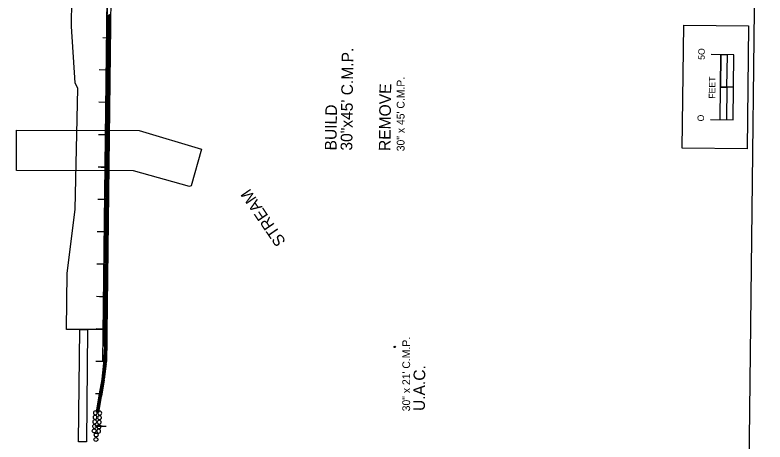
# Model space of a CAD drawing. Extents: x 16507806 to 16508824, y 7132703 to 7134669.
# Drawn here: x 16508245 to 16508824, y 7133461 to 7133791 of the extents above; entities that cross this region are included whole.
import ezdxf

# ---------------------------------------------------------------- set-up
doc = ezdxf.new("R2010")
doc.units = 0
for name, color, linetype in [('Default', 7, 'Continuous'), ('dsnCellElements', 7, 'Continuous'), ('dsnCellsScaleBlock', 7, 'Continuous'), ('EdgeShoulder', 7, 'Continuous'), ('NamedBoundary', 7, 'Continuous'), ('phoCulvert', 7, 'Continuous'), ('Shape', 7, 'Continuous'), ('SurSurveyPoints', 7, 'Continuous'), ('SurTxtDrainage', 7, 'Continuous'), ('Text', 7, 'Continuous'), ('TextAlignmentLrg', 7, 'Continuous'), ('TextAlignmentSml', 7, 'Continuous')]:
    doc.layers.add(name, color=color, linetype=linetype)

msp = doc.modelspace()

# ---------------------------------------------------------------- linework, layer by layer
at = {"layer": 'Default'}
msp.add_line((16508312.56, 7133523.48), (16508317.36, 7133923.45), dxfattribs=at)
for centre in [(16508317.59, 7133778.27), (16508317.64, 7133778.27), (16508317.44, 7133765.47), (16508317.44, 7133765.47), (16508317.29, 7133752.67), (16508317.29, 7133752.67), (16508317.11, 7133739.9), (16508317.15, 7133739.86), (16508316.96, 7133727.1), (16508316.96, 7133727.1), (16508316.82, 7133714.3), (16508316.82, 7133714.3), (16508316.67, 7133701.5), (16508316.67, 7133701.5), (16508316.52, 7133688.7), (16508316.52, 7133688.7), (16508316.38, 7133675.9), (16508316.38, 7133675.9), (16508316.23, 7133663.09), (16508316.23, 7133663.09), (16508316.08, 7133650.29), (16508316.08, 7133650.29), (16508315.94, 7133637.49), (16508315.94, 7133637.49), (16508315.79, 7133624.69), (16508315.79, 7133624.69), (16508315.64, 7133611.89), (16508315.64, 7133611.89), (16508315.5, 7133599.09), (16508315.5, 7133599.09), (16508315.35, 7133586.29), (16508315.35, 7133586.29), (16508315.15, 7133573.49), (16508315.2, 7133573.49), (16508315, 7133560.68), (16508315.06, 7133560.68), (16508314.91, 7133547.88)]:
    msp.add_circle(centre, 0.0521, dxfattribs=at)
for centre, start, end in [((16508317.78, 7133790.92), 359.34293, 179.34293), ((16508317.59, 7133778.12), 359.34293, 179.34293), ((16508317.64, 7133778.42), 179.34293, 359.34293), ((16508317.44, 7133765.62), 179.34293, 359.34293), ((16508317.44, 7133765.32), 359.34293, 179.34293), ((16508317.3, 7133752.82), 179.34293, 359.34293), ((16508317.29, 7133752.52), 359.34293, 179.34293), ((16508317.11, 7133739.75), 359.34293, 179.34293), ((16508317.15, 7133740.02), 179.34293, 359.34293), ((16508316.97, 7133727.25), 179.34293, 359.34293), ((16508316.96, 7133726.95), 359.34293, 179.34293), ((16508316.82, 7133714.15), 359.34293, 179.34293), ((16508316.82, 7133714.45), 179.34293, 359.34293), ((16508316.67, 7133701.65), 179.34293, 359.34293), ((16508316.67, 7133701.35), 359.34293, 179.34293), ((16508316.53, 7133688.85), 179.34293, 359.34293), ((16508316.52, 7133688.55), 359.34293, 179.34293), ((16508316.37, 7133675.74), 359.34293, 179.34293), ((16508316.38, 7133676.05), 179.34293, 359.34293), ((16508316.23, 7133663.25), 179.34293, 359.34293), ((16508316.23, 7133662.94), 359.34293, 179.34293), ((16508316.08, 7133650.44), 179.34293, 359.34293), ((16508316.08, 7133650.14), 359.34293, 179.34293), ((16508315.93, 7133637.34), 359.34293, 179.34293), ((16508315.94, 7133637.64), 179.34293, 359.34293), ((16508315.79, 7133624.84), 179.34293, 359.34293), ((16508315.79, 7133624.54), 359.34293, 179.34293), ((16508315.64, 7133612.04), 179.34293, 359.34293), ((16508315.64, 7133611.74), 359.34293, 179.34293), ((16508315.49, 7133598.94), 359.34293, 179.34293), ((16508315.5, 7133599.24), 179.34293, 359.34293), ((16508315.35, 7133586.44), 179.34293, 359.34293), ((16508315.35, 7133586.14), 359.34293, 179.34293), ((16508315.15, 7133573.33), 359.34293, 179.34293), ((16508315.2, 7133573.64), 179.34293, 359.34293), ((16508315, 7133560.84), 179.34293, 359.34293), ((16508315.05, 7133560.53), 359.34293, 179.34293), ((16508314.91, 7133548.03), 179.34293, 359.34293)]:
    msp.add_arc(centre, 0.281, start, end, dxfattribs=at)
at = {"layer": 'dsnCellElements'}
for p, q in [((16508316.7, 7133778.43), (16508316.85, 7133790.93)), ((16508318.72, 7133790.91), (16508316.85, 7133790.93)), ((16508317.3, 7133778.42), (16508317.45, 7133790.92)), ((16508317.98, 7133778.42), (16508318.12, 7133790.91)), ((16508318.58, 7133778.41), (16508318.72, 7133790.91)), ((16508316.5, 7133765.63), (16508316.65, 7133778.13)), ((16508318.52, 7133778.11), (16508316.65, 7133778.13)), ((16508318.58, 7133778.41), (16508316.7, 7133778.43)), ((16508317.1, 7133765.62), (16508317.25, 7133778.12)), ((16508317.78, 7133765.61), (16508317.92, 7133778.11)), ((16508318.38, 7133765.61), (16508318.52, 7133778.11)), ((16508316.36, 7133752.83), (16508316.5, 7133765.33)), ((16508318.38, 7133765.61), (16508316.5, 7133765.63)), ((16508318.38, 7133765.31), (16508316.5, 7133765.33)), ((16508316.96, 7133752.82), (16508317.1, 7133765.32)), ((16508317.63, 7133752.81), (16508317.78, 7133765.31)), ((16508318.23, 7133752.81), (16508318.38, 7133765.31)), ((16508316.21, 7133740.03), (16508316.35, 7133752.53)), ((16508318.23, 7133752.5), (16508316.35, 7133752.53)), ((16508318.23, 7133752.81), (16508316.36, 7133752.83)), ((16508316.81, 7133740.02), (16508316.95, 7133752.52)), ((16508317.49, 7133740.01), (16508317.63, 7133752.51)), ((16508318.09, 7133740.01), (16508318.23, 7133752.5)), ((16508316.03, 7133727.26), (16508316.17, 7133739.76)), ((16508318.05, 7133739.74), (16508316.17, 7133739.76)), ((16508318.09, 7133740.01), (16508316.21, 7133740.03)), ((16508316.63, 7133727.26), (16508316.77, 7133739.76)), ((16508317.3, 7133727.25), (16508317.45, 7133739.75)), ((16508317.9, 7133727.24), (16508318.05, 7133739.74)), ((16508315.88, 7133714.46), (16508316.02, 7133726.96)), ((16508317.9, 7133726.94), (16508316.02, 7133726.96)), ((16508317.9, 7133727.24), (16508316.03, 7133727.26)), ((16508316.48, 7133714.45), (16508316.62, 7133726.95)), ((16508317.16, 7133714.45), (16508317.3, 7133726.95)), ((16508317.76, 7133714.44), (16508317.9, 7133726.94)), ((16508315.73, 7133701.66), (16508315.88, 7133714.16)), ((16508317.76, 7133714.44), (16508315.88, 7133714.46)), ((16508317.75, 7133714.14), (16508315.88, 7133714.16)), ((16508316.33, 7133701.65), (16508316.48, 7133714.15)), ((16508317.01, 7133701.65), (16508317.15, 7133714.14)), ((16508317.61, 7133701.64), (16508317.75, 7133714.14)), ((16508315.59, 7133688.86), (16508315.73, 7133701.36)), ((16508317.61, 7133701.64), (16508315.73, 7133701.66)), ((16508317.61, 7133701.34), (16508315.73, 7133701.36)), ((16508316.19, 7133688.85), (16508316.33, 7133701.35)), ((16508316.86, 7133688.84), (16508317.01, 7133701.34)), ((16508317.46, 7133688.84), (16508317.61, 7133701.34)), ((16508315.44, 7133676.06), (16508315.58, 7133688.56)), ((16508317.46, 7133688.54), (16508315.58, 7133688.56)), ((16508317.46, 7133688.84), (16508315.59, 7133688.86)), ((16508316.04, 7133676.05), (16508316.18, 7133688.55)), ((16508316.72, 7133676.04), (16508316.86, 7133688.54)), ((16508317.32, 7133676.04), (16508317.46, 7133688.54)), ((16508315.29, 7133663.26), (16508315.44, 7133675.76)), ((16508317.32, 7133676.04), (16508315.44, 7133676.06)), ((16508317.31, 7133675.73), (16508315.44, 7133675.76)), ((16508315.89, 7133663.25), (16508316.04, 7133675.75)), ((16508316.57, 7133663.24), (16508316.71, 7133675.74)), ((16508317.17, 7133663.23), (16508317.31, 7133675.73)), ((16508315.15, 7133650.45), (16508315.29, 7133662.95)), ((16508317.17, 7133663.23), (16508315.29, 7133663.26)), ((16508317.17, 7133662.93), (16508315.29, 7133662.95)), ((16508315.75, 7133650.45), (16508315.89, 7133662.95)), ((16508316.42, 7133650.44), (16508316.57, 7133662.94)), ((16508317.02, 7133650.43), (16508317.17, 7133662.93)), ((16508315, 7133637.65), (16508315.14, 7133650.15)), ((16508317.02, 7133650.13), (16508315.14, 7133650.15)), ((16508317.02, 7133650.43), (16508315.15, 7133650.45)), ((16508315.6, 7133637.65), (16508315.74, 7133650.15)), ((16508316.28, 7133637.64), (16508316.42, 7133650.14)), ((16508316.88, 7133637.63), (16508317.02, 7133650.13)), ((16508316.88, 7133637.63), (16508315, 7133637.65)), ((16508314.85, 7133624.85), (16508315, 7133637.35)), ((16508316.87, 7133637.33), (16508315, 7133637.35)), ((16508315.45, 7133624.85), (16508315.6, 7133637.34)), ((16508316.13, 7133624.84), (16508316.27, 7133637.34)), ((16508316.73, 7133624.83), (16508316.87, 7133637.33)), ((16508314.71, 7133612.05), (16508314.85, 7133624.55)), ((16508316.73, 7133624.83), (16508314.85, 7133624.85)), ((16508316.72, 7133624.53), (16508314.85, 7133624.55)), ((16508315.31, 7133612.04), (16508315.45, 7133624.54)), ((16508315.98, 7133612.04), (16508316.12, 7133624.54)), ((16508316.58, 7133612.03), (16508316.72, 7133624.53)), ((16508314.56, 7133599.25), (16508314.7, 7133611.75)), ((16508316.58, 7133611.73), (16508314.7, 7133611.75)), ((16508316.58, 7133612.03), (16508314.71, 7133612.05)), ((16508315.16, 7133599.24), (16508315.3, 7133611.74)), ((16508315.83, 7133599.24), (16508315.98, 7133611.73)), ((16508316.43, 7133599.23), (16508316.58, 7133611.73)), ((16508314.41, 7133586.45), (16508314.56, 7133598.95)), ((16508316.43, 7133599.23), (16508314.56, 7133599.25)), ((16508316.43, 7133598.93), (16508314.56, 7133598.95)), ((16508315.01, 7133586.44), (16508315.16, 7133598.94)), ((16508315.69, 7133586.43), (16508315.83, 7133598.93)), ((16508316.29, 7133586.43), (16508316.43, 7133598.93)), ((16508314.27, 7133573.65), (16508314.41, 7133586.15)), ((16508316.29, 7133586.43), (16508314.41, 7133586.45)), ((16508316.28, 7133586.12), (16508314.41, 7133586.15)), ((16508314.87, 7133573.64), (16508315.01, 7133586.14)), ((16508315.54, 7133573.63), (16508315.68, 7133586.13)), ((16508316.14, 7133573.63), (16508316.28, 7133586.12)), ((16508314.07, 7133560.85), (16508314.21, 7133573.35)), ((16508316.09, 7133573.32), (16508314.21, 7133573.35)), ((16508316.14, 7133573.63), (16508314.27, 7133573.65)), ((16508314.67, 7133560.84), (16508314.81, 7133573.34)), ((16508315.34, 7133560.83), (16508315.49, 7133573.33)), ((16508315.94, 7133560.82), (16508316.09, 7133573.32)), ((16508313.97, 7133548.04), (16508314.12, 7133560.54)), ((16508315.94, 7133560.82), (16508314.07, 7133560.85)), ((16508315.99, 7133560.52), (16508314.12, 7133560.54)), ((16508314.57, 7133548.04), (16508314.72, 7133560.54)), ((16508315.25, 7133548.03), (16508315.39, 7133560.53)), ((16508315.85, 7133548.02), (16508315.99, 7133560.52)), ((16508313.77, 7133535.29), (16508313.91, 7133547.79)), ((16508313.91, 7133547.79), (16508315.79, 7133547.76)), ((16508315.85, 7133548.02), (16508313.97, 7133548.04)), ((16508314.37, 7133535.28), (16508314.51, 7133547.78)), ((16508315.04, 7133535.27), (16508315.19, 7133547.77)), ((16508315.64, 7133535.26), (16508315.79, 7133547.76)), ((16508313.77, 7133534.97), (16508313.21, 7133522.49)), ((16508313.77, 7133535.29), (16508315.64, 7133535.26)), ((16508315.64, 7133534.89), (16508313.77, 7133534.97)), ((16508314.37, 7133534.95), (16508313.81, 7133522.46)), ((16508315.04, 7133534.92), (16508314.49, 7133522.43)), ((16508315.64, 7133534.89), (16508315.09, 7133522.4)), ((16508313.2, 7133522.17), (16508311.84, 7133509.75)), ((16508313.8, 7133522.11), (16508312.44, 7133509.68)), ((16508314.47, 7133522.03), (16508313.11, 7133509.61)), ((16508315.06, 7133521.97), (16508313.2, 7133522.17)), ((16508315.09, 7133522.4), (16508313.21, 7133522.49)), ((16508315.06, 7133521.97), (16508313.7, 7133509.54)), ((16508311.81, 7133509.44), (16508309.62, 7133497.13)), ((16508312.4, 7133509.33), (16508310.21, 7133497.02)), ((16508313.06, 7133509.21), (16508310.88, 7133496.91)), ((16508313.65, 7133509.11), (16508311.47, 7133496.8)), ((16508313.65, 7133509.11), (16508311.81, 7133509.44)), ((16508313.7, 7133509.54), (16508311.84, 7133509.75)), ((16508309.57, 7133496.82), (16508307.39, 7133484.51)), ((16508310.16, 7133496.72), (16508307.98, 7133484.41)), ((16508310.83, 7133496.6), (16508308.64, 7133484.29)), ((16508311.42, 7133496.49), (16508309.23, 7133484.19)), ((16508311.42, 7133496.49), (16508309.57, 7133496.82)), ((16508311.47, 7133496.8), (16508309.62, 7133497.13)), ((16508309.23, 7133484.19), (16508307.39, 7133484.51))]:
    msp.add_line(p, q, dxfattribs=at)
msp.add_lwpolyline([(16508760.03, 7133688.07), (16508761.11, 7133783.07), (16508811.11, 7133782.5), (16508810.02, 7133687.5)], close=True, dxfattribs=at)
msp.add_lwpolyline([(16508760.03, 7133688.07), (16508761.11, 7133783.07), (16508811.11, 7133782.5), (16508810.02, 7133687.5)], close=True, dxfattribs=at)
at = {"layer": 'dsnCellsScaleBlock'}
msp.add_line((16508799.57, 7133735.13), (16508789.57, 7133735.24), dxfattribs=at)
msp.add_line((16508799.57, 7133735.13), (16508789.57, 7133735.24), dxfattribs=at)
for points in [[(16508810.02, 7133687.5), (16508760.03, 7133688.07), (16508761.11, 7133783.07), (16508811.11, 7133782.5)], [(16508794.53, 7133735.18), (16508794.82, 7133760.18), (16508789.85, 7133760.24), (16508789.57, 7133735.24)], [(16508799.28, 7133710.13), (16508799.57, 7133735.13), (16508794.53, 7133735.18), (16508794.25, 7133710.18)]]:
    msp.add_lwpolyline(points, close=True, dxfattribs=at)
for points in [[(16508781.78, 7133710.33), (16508799.28, 7133710.13), (16508799.85, 7133760.12), (16508782.35, 7133760.32)], [(16508789.28, 7133710.24), (16508789.85, 7133760.24)]]:
    msp.add_lwpolyline(points, dxfattribs=at)
at = {"layer": 'EdgeShoulder'}
msp.add_lwpolyline([(16508293.92, 7133461.45), (16508294.86, 7133548.12), (16508300.86, 7133548.05), (16508299.91, 7133461.39)], close=True, dxfattribs=at)
at = {"layer": 'NamedBoundary'}
msp.add_lwpolyline([(16507805.91, 7132945.52), (16508805.85, 7132934.01), (16508823.89, 7134501.41), (16507823.95, 7134512.92)], close=True, dxfattribs=at)
at = {"layer": 'phoCulvert'}
for centre in [(16508305.89, 7133469.84), (16508305.89, 7133469.84), (16508307.23, 7133463.21), (16508307.45, 7133466.71)]:
    msp.add_circle(centre, 1.5, dxfattribs=at)
for centre, start, end in [((16508306.54, 7133480.32), 91.4352, 271.4352), ((16508306.76, 7133483.81), 91.4352, 271.4352), ((16508306.54, 7133480.32), 271.4352, 91.4352), ((16508306.76, 7133483.81), 271.4352, 91.4352), ((16508310.04, 7133480.1), 91.4352, 271.4352), ((16508310.25, 7133483.6), 91.4352, 271.4352), ((16508310.04, 7133480.1), 271.4352, 91.4352), ((16508310.25, 7133483.6), 271.4352, 91.4352), ((16508306.33, 7133476.83), 91.4352, 271.4352), ((16508306.33, 7133476.83), 271.4352, 91.4352), ((16508309.82, 7133476.61), 91.4352, 271.4352), ((16508309.82, 7133476.61), 271.4352, 91.4352), ((16508306.11, 7133473.33), 91.4352, 271.4352), ((16508306.11, 7133473.33), 271.4352, 91.4352), ((16508309.38, 7133469.62), 91.4352, 271.4352), ((16508309.6, 7133473.12), 91.4352, 271.4352), ((16508309.38, 7133469.62), 271.4352, 91.4352), ((16508309.6, 7133473.12), 271.4352, 91.4352)]:
    msp.add_arc(centre, 1.5, start, end, dxfattribs=at)
at = {"layer": 'Shape'}
msp.add_line((16508315.56, 7133523.44), (16508320.36, 7133923.41), dxfattribs=at)
for points in [[(16508300.86, 7133548.05), (16508284.43, 7133548.24), (16508285.15, 7133591.74), (16508291.03, 7133638.72), (16508291.33, 7133641.12), (16508293.17, 7133734.3), (16508291.24, 7133738.61), (16508288.34, 7133782.18), (16508288.88, 7133824.4), (16508316.16, 7133823.44), (16508312.86, 7133548.05)], [(16508336.28, 7133670.68), (16508336.28, 7133670.68), (16508246.03, 7133670.94), (16508246.03, 7133702.11), (16508340.76, 7133701.79), (16508340.76, 7133701.79), (16508388.79, 7133687.36), (16508380.78, 7133658.99), (16508379.56, 7133658.52)]]:
    msp.add_lwpolyline(points, close=True, dxfattribs=at)
at = {"layer": 'SurSurveyPoints'}
msp.add_circle((16508537.95, 7133534.73), 0.5, dxfattribs=at)
at = {"layer": 'TextAlignmentLrg'}
for p, q in [((16508312.52, 7133773.5), (16508318.64, 7133773.42)), ((16508314.37, 7133673.47), (16508308.91, 7133673.53)), ((16508313.16, 7133573.47), (16508307.7, 7133573.54)), ((16508311.97, 7133473.48), (16508306.51, 7133473.54))]:
    msp.add_line(p, q, dxfattribs=at)
at = {"layer": 'TextAlignmentSml'}
for p, q in [((16508312.52, 7133773.5), (16508318.64, 7133773.42)), ((16508315.27, 7133748.46), (16508309.81, 7133748.53)), ((16508314.97, 7133723.46), (16508309.51, 7133723.53)), ((16508314.67, 7133698.46), (16508309.21, 7133698.53)), ((16508311.31, 7133673.5), (16508317.43, 7133673.43)), ((16508314.07, 7133648.47), (16508308.61, 7133648.53)), ((16508313.76, 7133623.47), (16508308.31, 7133623.54)), ((16508313.46, 7133598.47), (16508308, 7133598.54)), ((16508310.1, 7133573.51), (16508316.22, 7133573.44)), ((16508312.86, 7133548.47), (16508307.4, 7133548.54)), ((16508312.56, 7133523.48), (16508307.1, 7133523.54)), ((16508312.26, 7133498.48), (16508306.8, 7133498.54)), ((16508308.91, 7133473.51), (16508315.03, 7133473.45))]:
    msp.add_line(p, q, dxfattribs=at)

# ---------------------------------------------------------------- texts
at = {"layer": 'dsnCellsScaleBlock'}
for s, p in [('5O', (16508777.3, 7133756.31)), ('FEET', (16508785.46, 7133726.31)), ('O', (16508776.76, 7133708.75))]:
    msp.add_text(s, height=5, rotation=89.34703, dxfattribs=at).set_placement(p)
at = {"layer": 'SurTxtDrainage'}
for s, p in [('30" x 45\' C.M.P.', (16508545.54, 7133685.75)), ('30" x 21\' C.M.P.', (16508549.85, 7133485.01))]:
    msp.add_text(s, height=6, rotation=90.00652, dxfattribs=at).set_placement(p)
at = {"layer": 'Text'}
for s, rotation, p in [('30"x45\' C.M.P.', 89.34703, (16508505.18, 7133686.19)), ('REMOVE', 89.34703, (16508534.68, 7133685.85)), ('BUILD', 89.34703, (16508493, 7133686.32)), ('STREAM', 124.41441, (16508454.24, 7133616.14)), ('U.A.C.', 89.34703, (16508561.23, 7133485.16))]:
    msp.add_text(s, height=9, rotation=rotation, dxfattribs=at).set_placement(p)

doc.saveas('drawing.dxf')
